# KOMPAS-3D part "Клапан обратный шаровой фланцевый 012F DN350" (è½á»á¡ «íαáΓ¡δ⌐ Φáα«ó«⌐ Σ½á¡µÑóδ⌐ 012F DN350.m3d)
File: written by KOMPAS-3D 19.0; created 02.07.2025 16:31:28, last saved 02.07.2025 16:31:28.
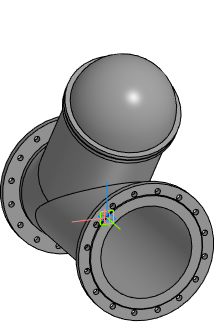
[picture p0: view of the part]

Document properties: Полное имя файла: E:\Dendor Работа Сачек\3D для проектировщиков\5.3 Тип 012F, 012F.Z Клапан обратный шаровой фланцевый\stp_Клапан обратный шаровой фланцевый 012F\Клапан обратный шаровой фланцевый 012F DN350.m3d

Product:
- Part/product: Клапан обратный шаровой фланцевый 012F DN350

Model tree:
1. Операция без истории:1  (labels: Клапан обратный шаровой фланцевый 012F DN350)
